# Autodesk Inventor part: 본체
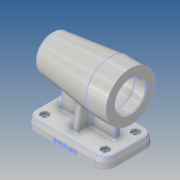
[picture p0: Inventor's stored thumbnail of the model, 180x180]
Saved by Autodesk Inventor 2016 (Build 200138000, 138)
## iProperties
Created: 2017-01
Part Number: 본체
Material: 알루미늄 6061
Document SubType Name: Modeling
Designer: Administrator
Density: 2.7 g/cm^3
Appearance: 알루미늄 - 평지
Mass: 792.236 g
Surface Area: 661.853 cm^2
Volume: 293.421 cm^3
Author: Administrator
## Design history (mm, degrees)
sketch "스케치1"
  geometry: L1 (-42, -35)-(42, -35); L2 (56, -21)-(56, 21); L3 (42, 35)-(-42, 35); L4 (-56, 21)-(-56, -21); L5 (-56, -35)-(56, 35); L6 (56, -35)-(-56, 35); A1 r 14 centre (-42, 21) between (-42, 35) and (-56, 21); A2 r 14 centre (42, 21) between (56, 21) and (42, 35); A3 r 14 centre (42, -21) between (42, -35) and (56, -21); A4 r 14 centre (-42, -21) between (-56, -21) and (-42, -35); 1 further point
  constraints: 12 end point, 8 point on circle, 8 point on line, 8 tangent, 4 centre point, 3 equal radius, 2 midpoint, 2 parallel, 1 horizontal, 1 perpendicular
  dimensions: "d0" = 112 distance of L5.end L6.end; "d1" = 70 distance of L6.start L5.end; "d2" = 14 radius of A1
extrude "돌출1" new body sketch "스케치1" distance "d3" = 7; taper "d4" = 0 deg
sketch "스케치2"
  geometry: L1 (-56, 21)-(-56, -21) reference; L2 (-42, -35)-(42, -35) reference; L3 (56, -21)-(56, 21) reference; L4 (42, 35)-(-42, 35) reference; L5 (-42, -35)-(42, -35); L6 (56, -21)-(56, 21); L7 (42, 35)-(-42, 35); L8 (-56, 21)-(-56, -21); L9 (-56, -35)-(56, 35); L10 (56, -35)-(-56, 35); A1 r 14 centre (-42, -21) between (-56, -21) and (-42, -35) reference; A2 r 14 centre (42, -21) between (42, -35) and (56, -21) reference; A3 r 14 centre (42, 21) between (56, 21) and (42, 35) reference; A4 r 14 centre (-42, 21) between (-42, 35) and (-56, 21) reference; A5 r 14 centre (-42, 21) between (-42, 35) and (-56, 21); A6 r 14 centre (42, 21) between (56, 21) and (42, 35); A7 r 14 centre (42, -21) between (42, -35) and (56, -21); A8 r 14 centre (-42, -21) between (-56, -21) and (-42, -35); 1 further point
  constraints: 12 end point, 8 point on circle, 8 point on line, 8 tangent, 4 centre point, 3 equal radius, 2 midpoint, 2 parallel, 1 horizontal, 1 perpendicular
  dimensions: "d5" = 112 distance of L9.end L10.end; "d6" = 70 distance of L10.end L9.start; "d7" = 14 radius of A5
extrude "돌출2" join sketch "스케치2" distance "d8" = 7; taper "d9" = -15 deg
sketch "스케치3"
  geometry: L1 (56, 74)-(-56, 74); L2 (-42, 0)-(42, 0) reference; L3 (56, 0)-(56, 7) reference; L4 (-56, 0)-(-56, 7) reference; L5 (-56, 74)-(-56, 108); L6 (-56, 108)-(-28, 108); L7 (-28, 108)-(52.27, 98.144); L8 (56, 74)-(-24, 74); A1 r 80 centre (-24, 74) between (56, 74) and (52.27, 98.144); 3 further points
  constraints: 10 end point, 2 midpoint, 2 point on circle, 1 centre point, 1 coincident, 1 horizontal, 1 perpendicular, 1 point on line, 1 vertical, 1 vertical alignment
  dimensions: "d10" = 74 distance between parallel lines of L1 L2; "d11" = 112 distance of L1.start L1.end; "d13" = 80 distance of L1.start L8.end; "d14" = 7 deg angle of L6 L7; "d15" = 68 diameter of L6 L1; "d16" = 28 distance from line of L6.end L5
revolve "회전1" sketch "스케치3" stored, may be unused: angle "d17" = 90 deg
sketch "스케치4"
  geometry: L1 (56, 0)-(42, 0) reference; L2 (-42, 0)-(42, 0) reference; L3 (-56, 0)-(-42, 0) reference; L4 (-42, 0)-(-42, 7) reference; L5 (-56, 7)-(-42, 7) reference; L6 (-56, 0)-(-56, 7) reference; L7 (-42, 0)-(-56, 0) reference; L8 (38, 0)-(38, 73); L9 (-38, 0)-(-38, 73); L10 (-38, 73)-(38, 73); L11 (56, 0)-(56, 7) reference; 1 further point
  constraints: 6 end point, 2 point on line, 2 vertical, 1 perpendicular
  dimensions: "d18" = 18 distance between parallel lines of L8 L11; "d19" = 18 distance between parallel lines of L6 L9; "d20" = 73 distance between parallel lines of L2 L10
extrude "돌출3" join sketch "스케치4" stored distance "d21" = 8; taper "d22" = 0 deg
sketch "스케치5"
  geometry: L1 (-33.124, 14)-(-21, 14) reference; L2 (-21, 14)-(21, 14) reference; L3 (21, 14)-(33.124, 14) reference; L4 (-23, 14)-(-14.184, 64); L5 (-14.184, 64)-(14.184, 64); L6 (14.184, 64)-(23, 14); L7 (35, 0)-(35, 7) reference; L8 (-35, 0)-(-35, 7) reference; 1 further point
  constraints: 6 end point, 2 point on line, 1 horizontal
  dimensions: "d23" = 12 horizontal distance of L7.start L6.end; "d24" = 12 horizontal distance of L4.start L8.start; "d25" = 100 deg angle of L1 L4; "d26" = 100 deg angle of L3 L6; "d27" = 50 distance between parallel lines of L2 L5
extrude "돌출4" join sketch "스케치5" stored distance "d28" = 8; taper "d29" = 0 deg
sketch "스케치6"
  geometry: L1 (-56, 40)-(-56, 108) reference; L2 (-56, 74)-(56, 74); L3 (-56, 95)-(-41, 95); L4 (-41, 95)-(-41, 98); L5 (-41, 98)-(13, 98); L6 (13, 98)-(13, 95); L7 (13, 95)-(25, 95); L8 (25, 95)-(25, 91.5); L9 (25, 91.5)-(43, 91.5); L10 (43, 91.5)-(43, 90); L11 (43, 90)-(47, 90); L12 (47, 90)-(47, 84.5); L13 (47, 84.5)-(50, 84.5); L14 (50, 84.5)-(50, 74); A1 r 80 centre (-24, 74) between (52.27, 49.856) and (52.27, 98.144) reference; 1 further point
  constraints: 26 end point, 8 perpendicular, 2 horizontal, 2 point on line, 1 midpoint, 1 parallel, 1 point on circle, 1 vertical
  dimensions: "d30" = 42 diameter of L3 L2; "d31" = 48 diameter of L5 L2; "d32" = 42 diameter of L7 L2; "d33" = 35 diameter of L9 L2; "d34" = 32 diameter of L11 L2; "d35" = 21 diameter of L13 L2; "d36" = 15 distance between parallel lines of L1 L4; "d37" = 4 distance between parallel lines of L10 L12; "d38" = 12 distance between parallel lines of L6 L8; "d39" = 18 distance between parallel lines of L10 L8; "d40" = 3 distance between parallel lines of L12 L14; "d41" = 54 distance of L4.end L5.end
revolve "회전2" sketch "스케치6" stored, may be unused: angle "d42" = 90 deg
sketch "스케치7"
  geometry: C1 r 21 at (0, 0) reference; 2 further points
  constraints: 1 horizontal alignment
  dimensions: "d43" = 26 distance of point (-26, 0) C1.centre
hole "구멍1" sketch "스케치7" at (-26, 0) diameter "d44" = 3.242; stored, may be unused: countersink angle "d48" = 90 deg, drill point angle "d50" = 118 deg; dims "d45" = 8, "d46" = 4, "d47" = 2, "d49" = 11
sketch "스케치8"
  geometry: L1 (98, 0)-(98, 7) reference; 2 further points
  constraints: 1 other
  dimensions: "d54" = 4 distance of point (42, 0) point (42, 4); "d55" = 56 distance from line of point (42, 4) L1
feature "엠보싱1" sketch "스케치8" dims "d0" = 112, "d1" = 70, "d2" = 14, "d56" = 0.5, "d57" = 0
sketch "스케치9"
  geometry: L1 (-36.226, 21)-(-39.113, 16); L2 (-39.113, 16)-(-44.887, 16); L3 (-44.887, 16)-(-47.774, 21); L4 (-47.774, 21)-(-44.887, 26); L5 (-44.887, 26)-(-39.113, 26); L6 (-39.113, 26)-(-36.226, 21); A1 r 12.124 centre (-42, 21) between (-42, 33.124) and (-54.124, 21) reference; 2 further points
  constraints: 12 end point, 1 coincident, 1 horizontal alignment, 13 other
  dimensions: "d58" = 10 distance between parallel lines of L5 L2
extrude "돌출5" cut sketch "스케치9" distance "d59" = 4; taper "d60" = 0 deg
sketch "스케치10"
  geometry: L1 (-47.774, 21)-(-36.226, 21); 2 further points
  constraints: 2 end point, 1 horizontal, 1 midpoint
hole "구멍2" sketch "스케치10" at (-42, 21) diameter "d61" = 5; stored, may be unused: countersink angle "d65" = 90 deg, drill point angle "d67" = 118 deg; dims "d62" = 8, "d63" = 4, "d64" = 2, "d66" = 11
fillet "모깎기1" dims "d68" = 0.3
fillet "모깎기2" dims "d69" = 3
fillet "모깎기3" dims "d70" = 1
fillet "모깎기4" dims "d71" = 3
fillet "모깎기5" dims "d72" = 3
fillet "모깎기6" dims "d73" = 3
chamfer "모따기1" distance "d74" = 1; stored, may be unused: second distance "d75" = 2, angle "d76" = 45 deg
node "솔리드1"
pattern_circular "원형 패턴1" dims angle "d52" = 360 deg
mirror "대칭1"
mirror "대칭2"
node "투영된 루프1"
